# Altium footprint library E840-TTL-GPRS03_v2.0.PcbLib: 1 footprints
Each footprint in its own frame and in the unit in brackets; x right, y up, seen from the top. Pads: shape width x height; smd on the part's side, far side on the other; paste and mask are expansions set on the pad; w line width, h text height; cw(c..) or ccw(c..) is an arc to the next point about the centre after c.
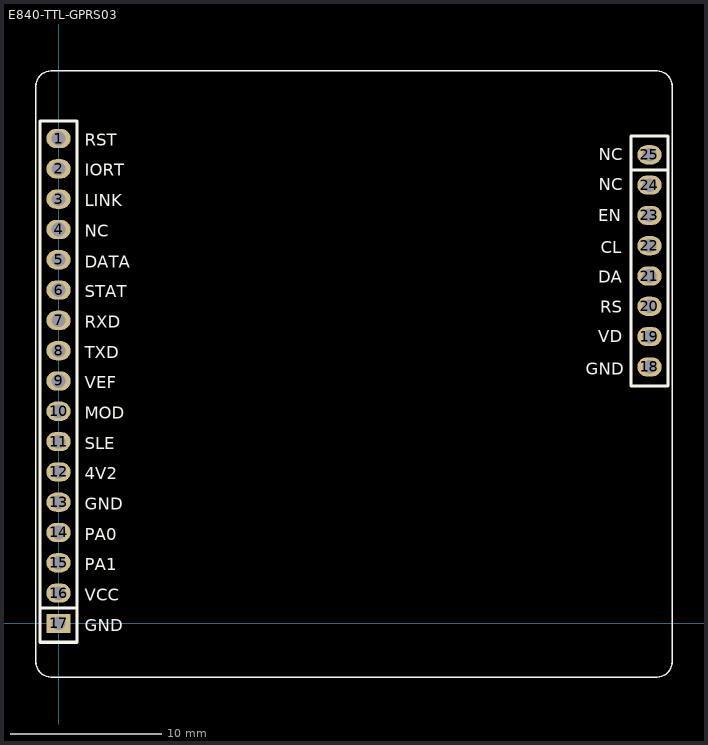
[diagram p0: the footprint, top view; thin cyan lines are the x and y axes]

## E840-TTL-GPRS03 [mm]
pads (25):
  oval 1.6x1.27 hole 0.9: 1(0,32) 2(0,30) 3(0,28) 4(0,26) 5(0,24) 6(0,22) 7(0,20) 8(0,18) 9(0,16) 10(0,14) 11(0,12) 12(0,10) 13(0,8) 14(0,6) 15(0,4) 16(0,2) 18(39,16.928) 19(39,18.928) 20(39,20.928) 21(39,22.928) 22(39,24.928) 23(39,26.928) 24(39,28.928) 25(39,30.928)
  rect 1.6x1.27 hole 0.9: 17(0,0)
Top Overlay:
  lines w0.1: -1.5,-2.54 ccw(c-0.5,-2.54) -0.5,-3.54 39.5,-3.54 ccw(c39.5,-2.54) 40.5,-2.54 40.5,35.46 ccw(c39.5,35.46) 39.5,36.46 -0.5,36.46 ccw(c-0.5,35.46) -1.5,35.46 -1.5,-2.54
  lines w0.203: -1.219,1.016 1.219,1.016 ; 37.781,29.912 40.219,29.912 ; 40.194,15.658 37.781,15.658 37.781,32.173 40.219,32.173 40.219,15.658 ; -1.219,-1.245 1.219,-1.245 1.219,33.16 -1.219,33.16 -1.219,-1.245
  text "NC" at 35.665,30.57 h0.8
  text "NC" at 35.665,28.58 h0.8
  text "EN" at 35.615,26.528 h0.8
  text "CL" at 35.802,24.42 h0.8
  text "DA" at 35.619,22.48 h0.8
  text "RS" at 35.737,20.49 h0.8
  text "VD" at 35.623,18.56 h0.8
  text "GND" at 34.8,16.42 h0.8
  text "GND" at 1.74,-0.53 h0.8
  text "VCC" at 1.74,1.492 h0.8
  text "PA1" at 1.74,3.494 h0.8
  text "PA0" at 1.74,5.496 h0.8
  text "GND" at 1.74,7.498 h0.8
  text "4V2" at 1.74,9.5 h0.8
  text "SLE" at 1.74,11.502 h0.8
  text "MOD" at 1.74,13.504 h0.8
  text "VEF" at 1.74,15.505 h0.8
  text "TXD" at 1.74,17.507 h0.8
  text "RXD" at 1.74,19.509 h0.8
  text "STAT" at 1.74,21.511 h0.8
  text "DATA" at 1.74,23.47 h0.8
  text "NC" at 1.74,25.515 h0.8
  text "LINK" at 1.74,27.517 h0.8
  text "IORT" at 1.74,29.53 h0.8
  text "RST" at 1.74,31.52 h0.8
